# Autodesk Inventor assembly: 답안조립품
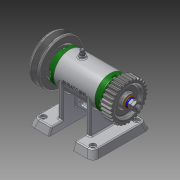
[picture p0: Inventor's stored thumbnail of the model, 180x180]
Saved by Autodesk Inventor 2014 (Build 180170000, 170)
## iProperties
Created: 2016-07
Part Number: 답안조립품
Document SubType Name: Assembly
Designer: basic
Author: basic
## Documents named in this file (16)
- C:\Users\basic\Desktop\460708V1008\답안조립품.iam
- C:\Users\basic\Desktop\460708V1008\본체.ipt
- C:\Users\basic\Desktop\460708V1008\커버.ipt
- C:\Users\basic\Desktop\460708V1008\베어링 15 x 32 x 9.ipt
- C:\Users\basic\Desktop\460708V1008\오일 실 15 25 7.ipt
- C:\Users\basic\Desktop\460708V1008\축.ipt
- C:\Users\basic\Desktop\460708V1008\키 3 x 3 x 12.ipt
- C:\Users\basic\Desktop\460708V1008\니플 M 6 x 0.75.ipt
- C:\Users\basic\Desktop\460708V1008\V벨트풀리.ipt
- C:\Users\basic\Desktop\460708V1008\스퍼기어.ipt
- C:\Users\basic\Desktop\460708V1008\와셔 8x17.ipt
- C:\Users\basic\Desktop\460708V1008\너트 M 8.ipt
- C:\Users\basic\Desktop\460708V1008\스프링와셔 8.ipt
- C:\Users\basic\Desktop\460708V1008\와셔 6x11.5.ipt
- C:\Users\basic\Desktop\460708V1008\볼트 M 6 x 8.ipt
- C:\Users\basic\Desktop\460708V1008\볼트 M4 x 12.ipt
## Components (11 placed, 3 different names)
1. KS B 2023 6002 - 15 x 32 x 9:1
2. KS B 2023 6002 - 15 x 32 x 9:2
3. V벨트풀리:1
4. ISO 4762 M4 x 12:2
5. ISO 4762 M4 x 12:3
6. ISO 4762 M4 x 12:4
7. ISO 4762 M4 x 12:5
8. ISO 4762 M4 x 12:1
9. ISO 4762 M4 x 12:6
10. ISO 4762 M4 x 12:7
11. ISO 4762 M4 x 12:8
